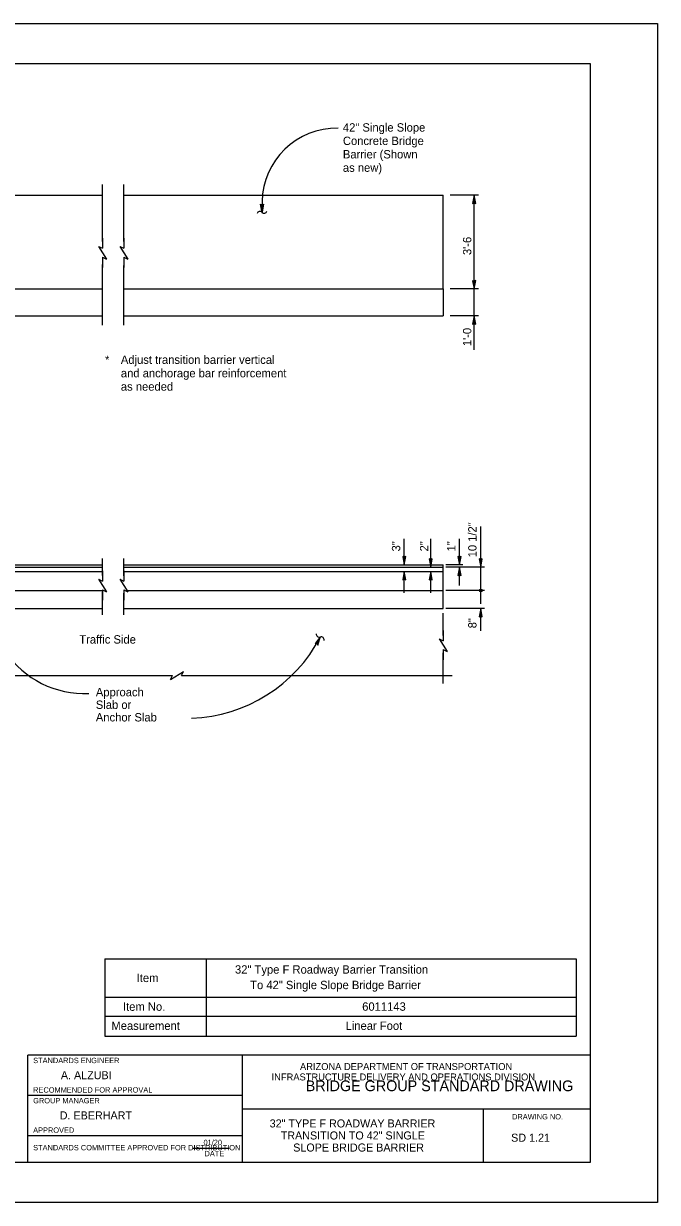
# Model space of a CAD drawing. Extents: x 0 to 2.83, y -0.03 to 1.83.
# Drawn here: x 1.848 to 2.833, y 0 to 1.833 of the extents above; entities that cross this region are included whole.
import ezdxf

# ---------------------------------------------------------------- set-up
doc = ezdxf.new("R2010")
doc.units = 0
for name, color, linetype in [('50', 7, 'Continuous'), ('54', 7, 'Continuous'), ('55', 7, 'Continuous'), ('57', 7, 'Continuous'), ('62', 7, 'Continuous'), ('63', 7, 'Continuous')]:
    doc.layers.add(name, color=color, linetype=linetype)

msp = doc.modelspace()

# ---------------------------------------------------------------- linework, layer by layer
at = {"layer": '50'}
for p, q in [((1.5072, 1.5665), (1.9702, 1.5665)), ((2.0036, 1.5665), (2.5, 1.5665)), ((2.5, 1.4207), (2.5, 1.5665)), ((1.5072, 1.4207), (1.9702, 1.4207)), ((2.0036, 1.4207), (2.5, 1.4207)), ((2.5, 1.4207), (2.5, 1.379)), ((1.5072, 1.379), (1.9702, 1.379)), ((2.0036, 1.379), (2.5, 1.379)), ((0.8822, 0.9914), (1.9702, 0.9914)), ((2.0036, 0.9914), (2.5, 0.9914)), ((2.5, 0.9237), (2.5, 0.9914)), ((1.5072, 0.981), (1.9702, 0.981)), ((1.5141, 0.9879), (1.9702, 0.9879)), ((2.0036, 0.9879), (2.5, 0.9879)), ((2.0036, 0.9879), (2.5, 0.9879)), ((2.0038, 0.981), (2.5, 0.981)), ((1.5072, 0.9515), (1.9702, 0.9515)), ((2.0086, 0.9515), (2.5, 0.9515)), ((0.8822, 0.9237), (1.9702, 0.9237)), ((2.0036, 0.9237), (2.5, 0.9237))]:
    msp.add_line(p, q, dxfattribs=at)
at = {"layer": '54'}
for points in [[(2.5484, 1.5665), (2.546, 1.5535), (2.5484, 1.555), (2.5508, 1.5536)], [(2.5484, 1.4207), (2.5508, 1.4336), (2.5484, 1.4321), (2.546, 1.4335)], [(2.5484, 1.379), (2.546, 1.366), (2.5484, 1.3675), (2.5508, 1.3661)], [(2.4397, 0.9914), (2.442, 1.0044), (2.4397, 1.0029), (2.4373, 1.0043)], [(2.4809, 0.9879), (2.4832, 1.0009), (2.4809, 0.9994), (2.4785, 1.0008)], [(2.5255, 0.9914), (2.5279, 1.0044), (2.5255, 1.0029), (2.5231, 1.0043)], [(2.5586, 0.9879), (2.561, 1.0009), (2.5586, 0.9994), (2.5562, 1.0008)], [(2.4397, 0.981), (2.4373, 0.968), (2.4397, 0.9695), (2.4421, 0.9682)], [(2.4808, 0.981), (2.4785, 0.968), (2.4808, 0.9695), (2.4832, 0.9682)], [(2.5255, 0.9879), (2.5231, 0.975), (2.5255, 0.9765), (2.5279, 0.9751)], [(2.5586, 0.9238), (2.5562, 0.9108), (2.5586, 0.9123), (2.561, 0.9109)]]:
    msp.add_lwpolyline(points, close=True, dxfattribs=at)
at = {"layer": '55'}
for p, q in [((1.9702, 1.4946), (1.9702, 1.583)), ((2.0036, 1.4946), (2.0036, 1.583)), ((2.5551, 1.5665), (2.5109, 1.5665)), ((2.5484, 1.4207), (2.5484, 1.5665)), ((2.2184, 1.5564), (2.2184, 1.5398)), ((1.964, 1.4869), (1.9702, 1.4838)), ((1.964, 1.4869), (1.9764, 1.467)), ((1.9702, 1.4997), (1.9702, 1.4838)), ((1.9974, 1.4869), (2.0036, 1.4838)), ((1.9974, 1.4869), (2.0097, 1.467)), ((2.0036, 1.4997), (2.0036, 1.4838)), ((1.9702, 1.47), (1.9764, 1.467)), ((1.9702, 1.47), (1.9702, 1.4541)), ((2.0036, 1.47), (2.0097, 1.467)), ((2.0036, 1.47), (2.0036, 1.4541)), ((1.9702, 1.3641), (1.9702, 1.4584)), ((2.0036, 1.3641), (2.0036, 1.4569)), ((2.5551, 1.4207), (2.5109, 1.4207)), ((2.5484, 1.3257), (2.5484, 1.4207)), ((2.5551, 1.379), (2.5109, 1.379)), ((2.5586, 0.9879), (2.5586, 1.0514)), ((2.4397, 0.9914), (2.4397, 1.0318)), ((2.4809, 0.9879), (2.4809, 1.0318)), ((2.5255, 0.9914), (2.5255, 1.0318)), ((1.9702, 0.9748), (1.9702, 1.0015)), ((2.0036, 0.9744), (2.0036, 1.0015)), ((2.5308, 0.9914), (2.5043, 0.9914)), ((1.9702, 0.9823), (1.9702, 0.9664)), ((2.0036, 0.9823), (2.0036, 0.9664)), ((2.4397, 0.9479), (2.4397, 0.981)), ((2.4808, 0.9479), (2.4808, 0.981)), ((2.5644, 0.9879), (2.5043, 0.9879)), ((2.5255, 0.9592), (2.5255, 0.9879)), ((2.5586, 0.9307), (2.5586, 0.9879)), ((1.964, 0.9695), (1.9702, 0.9664)), ((1.964, 0.9695), (1.9764, 0.9496)), ((1.9974, 0.9695), (2.0036, 0.9664)), ((1.9974, 0.9695), (2.0097, 0.9496)), ((1.9702, 0.9527), (1.9764, 0.9496)), ((1.9702, 0.9527), (1.9702, 0.9368)), ((1.9702, 0.9136), (1.9702, 0.9496)), ((2.0036, 0.9527), (2.0097, 0.9496)), ((2.0036, 0.9527), (2.0036, 0.9368)), ((2.0036, 0.9136), (2.0036, 0.9476)), ((2.5644, 0.9515), (2.5043, 0.9515)), ((2.5644, 0.9238), (2.5043, 0.9238)), ((2.5586, 0.889), (2.5586, 0.9238)), ((2.5, 0.8815), (2.5, 0.9166)), ((2.5, 0.8894), (2.5, 0.8735)), ((2.4938, 0.8766), (2.5, 0.8735)), ((2.4938, 0.8766), (2.5061, 0.8567)), ((2.5, 0.8598), (2.5061, 0.8567)), ((2.5, 0.8598), (2.5, 0.8439)), ((2.5, 0.807), (2.5, 0.8547)), ((2.0762, 0.8131), (2.0961, 0.8255)), ((2.093, 0.8193), (2.0961, 0.8255)), ((1.432, 0.8194), (2.0686, 0.8194)), ((2.0634, 0.8193), (2.0793, 0.8193)), ((2.0762, 0.8131), (2.0793, 0.8193)), ((2.093, 0.8193), (2.1089, 0.8193)), ((2.0968, 0.8194), (2.5142, 0.8194))]:
    msp.add_line(p, q, dxfattribs=at)
for points in [[(2.2184, 1.5397), (2.216, 1.5527), (2.2179, 1.5515), (2.2184, 1.5428), (2.2189, 1.5515), (2.2207, 1.5527), (2.2184, 1.5398)], [(2.2178, 1.5446), (2.2175, 1.5509), (2.2166, 1.5515), (2.2184, 1.5412), (2.2201, 1.5516), (2.2192, 1.5509), (2.219, 1.5448)], [(2.309, 0.8793), (2.3009, 0.8689), (2.3031, 0.869), (2.3076, 0.8766), (2.304, 0.8686), (2.3051, 0.8667), (2.3089, 0.8792)], [(2.3062, 0.8752), (2.3031, 0.8697), (2.302, 0.8696), (2.3083, 0.878), (2.305, 0.868), (2.3045, 0.869), (2.3071, 0.8745)]]:
    msp.add_lwpolyline(points, dxfattribs=at)
msp.add_circle((2.5586, 0.9515), 0.00214, dxfattribs=at)
for centre, radius, start, end in [((2.3351, 1.5541), 0.1167, 89.1633, 178.8612), ((2.2151, 1.5364), 0.0047, 44.9538, 161.3599), ((2.2217, 1.5431), 0.0047, 224.9538, 341.3599), ((2.3075, 0.8837), 0.0047, 171.3846, 287.7906), ((2.1013, 0.9873), 0.2341, 271.8499, 332.4926), ((2.3104, 0.8748), 0.0047, 351.3846, 107.7906), ((1.9416, 0.9388), 0.1473, 214.0105, 272.8594)]:
    msp.add_arc(centre, radius, start, end, dxfattribs=at)
at = {"layer": '57'}
for p, q in [((1.9739, 0.3789), (2.7072, 0.3789)), ((1.9739, 0.3789), (1.9739, 0.2585)), ((2.1316, 0.3789), (2.1316, 0.2585)), ((2.7072, 0.3789), (2.7072, 0.2585)), ((1.9739, 0.319), (2.7072, 0.319)), ((1.9739, 0.2898), (2.7072, 0.2898)), ((1.9739, 0.2585), (2.7072, 0.2585))]:
    msp.add_line(p, q, dxfattribs=at)
at = {"layer": '62'}
for p, q in [((2.7292, 0.2291), (1.8542, 0.2291)), ((1.8542, 0.0624), (1.8542, 0.2291)), ((2.1875, 0.2291), (2.1875, 0.0624)), ((2.5625, 0.1458), (2.5625, 0.0624)), ((2.111, 0.0843), (2.1675, 0.0843))]:
    msp.add_line(p, q, dxfattribs=at)
at = {"layer": '63'}
for p, q in [((0, 1.8333), (2.8333, 1.8333)), ((2.8333, 1.8333), (2.8333, 0)), ((1.8542, 0.1666), (2.1875, 0.1666)), ((2.1875, 0.1458), (2.7292, 0.1458)), ((1.8542, 0.1041), (2.1875, 0.1041)), ((2.8333, 0), (0, 0))]:
    msp.add_line(p, q, dxfattribs=at)
msp.add_lwpolyline([(2.7292, 1.7708), (0.1042, 1.7708), (0.1042, 0.0624), (2.7292, 0.0624)], close=True, dxfattribs=at)

# ---------------------------------------------------------------- texts
at = {"layer": '57'}
for s, height, p in [('42" Single Slope', 0.013021, (2.3442, 1.6653)), ('Concrete Bridge', 0.013021, (2.3442, 1.6445)), ('Barrier (Shown ', 0.013021, (2.3442, 1.6236)), ('as new)', 0.01302, (2.3442, 1.6028)), ('*', 0.013, (1.9743, 1.3041)), ('Adjust transition barrier vertical ', 0.013021, (1.9989, 1.3041)), ('and anchorage bar reinforcement ', 0.013021, (1.9989, 1.2832)), ('as needed', 0.01302, (1.9989, 1.2624)), ('Traffic Side', 0.013021, (1.9342, 0.8691)), ('Approach', 0.01302, (1.96, 0.7871)), ('Slab or', 0.01302, (1.96, 0.7675)), ('Anchor Slab', 0.013025, (1.96, 0.748)), ('32" Type F Roadway Barrier Transition ', 0.013021, (2.1764, 0.3558)), ('Item', 0.01302, (2.0235, 0.3427)), ('To 42" Single Slope Bridge Barrier', 0.013021, (2.2, 0.3317)), ('Item No.  ', 0.01302, (2.0022, 0.298)), ('6011143', 0.01302, (2.3742, 0.2981)), ('Measurement', 0.013021, (1.9842, 0.2683)), ('Linear Foot', 0.013021, (2.3484, 0.2683))]:
    msp.add_text(s, height=height, dxfattribs=at).set_placement(p)
for s, p in [("3'-6", (2.5439, 1.4733)), ("1'-0", (2.5439, 1.3317)), ('10 1/2"', (2.552, 1.0033)), ('3"', (2.4334, 1.0124)), ('2"', (2.477, 1.0124)), ('1"', (2.5192, 1.0124)), ('8"', (2.552, 0.8929))]:
    msp.add_text(s, height=0.01297, rotation=90, dxfattribs=at).set_placement(p)
at = {"layer": '62'}
for s, height, p in [('STANDARDS ENGINEER', 0.008333, (1.8625, 0.2166)), ('     A. ALZUBI     ', 0.0125, (1.8824, 0.1916)), ('ARIZONA DEPARTMENT OF TRANSPORTATION', 0.010833, (2.2775, 0.2059)), ('INFRASTRUCTURE DELIVERY AND OPERATIONS DIVISION', 0.010833, (2.2333, 0.1897)), ('BRIDGE GROUP STANDARD DRAWING', 0.016667, (2.2864, 0.173)), ('RECOMMENDED FOR APPROVAL', 0.008333, (1.8625, 0.1708)), ('GROUP MANAGER', 0.008333, (1.8625, 0.1541)), ('     D. EBERHART      ', 0.0125, (1.8806, 0.1291)), ('32" TYPE F ROADWAY BARRIER', 0.0125, (2.2303, 0.1166)), ('DRAWING NO.', 0.008333, (2.6073, 0.1291)), ('APPROVED', 0.00833, (1.8625, 0.1083)), ('TRANSITION TO 42" SINGLE', 0.0125, (2.2475, 0.0979)), ('01/20', 0.00833, (2.1274, 0.0891)), ('SLOPE BRIDGE BARRIER', 0.0125, (2.2669, 0.0791)), (' SD 1.21 ', 0.0125, (2.6012, 0.0944)), ('STANDARDS COMMITTEE APPROVED FOR DISTRIBUTION', 0.008333, (1.8625, 0.081)), ('DATE', 0.00833, (2.129, 0.0718))]:
    msp.add_text(s, height=height, dxfattribs=at).set_placement(p)

doc.saveas('drawing.dxf')
